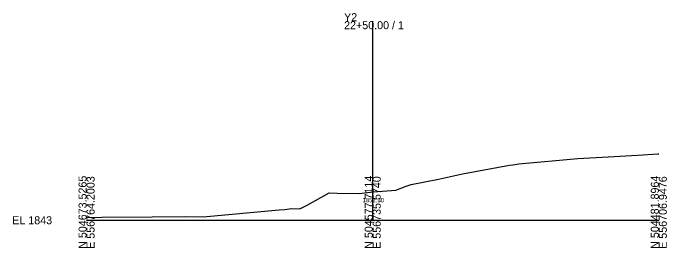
# Model space of a CAD drawing. Extents: x -26 to 1503, y -10 to 3574.
# Drawn here: x -25.7 to 202.8, y 2490.3 to 2572.5 of the extents above; entities that cross this region are included whole.
import ezdxf

# ---------------------------------------------------------------- set-up
doc = ezdxf.new("R2010")
doc.units = 0
for name, color, linetype in [('Default', 7, 'Continuous'), ('Exist Cross Section Cell', 7, 'Continuous'), ('Exist XS Center Line Elevation Label', 7, 'Continuous'), ('Exist XS Ground Line', 7, 'Continuous')]:
    doc.layers.add(name, color=color, linetype=linetype)

msp = doc.modelspace()

# ---------------------------------------------------------------- linework, layer by layer
at = {"layer": 'Exist Cross Section Cell'}
for p, q in [((100, 2500), (100, 2569.7)), ((0, 2500), (100, 2500)), ((100, 2500), (200, 2500))]:
    msp.add_line(p, q, dxfattribs=at)
at = {"layer": 'Exist XS Ground Line'}
for p, q in [((192.53, 2522.81), (199.62, 2523.21)), ((199.62, 2523.21), (200, 2523.23)), ((151.1, 2519.75), (171.67, 2521.65)), ((171.67, 2521.65), (182.26, 2522.17)), ((182.26, 2522.17), (192.53, 2522.81)), ((131.38, 2516.25), (147.87, 2519.26)), ((147.87, 2519.26), (148.96, 2519.45)), ((148.96, 2519.45), (151.1, 2519.75)), ((123.04, 2514.43), (131.38, 2516.25)), ((113.46, 2512.49), (123.04, 2514.43)), ((108.08, 2510.58), (111.73, 2511.9)), ((111.73, 2511.9), (113.46, 2512.49)), ((77.05, 2505.23), (84.73, 2509.64)), ((84.73, 2509.64), (87.63, 2509.51)), ((87.63, 2509.51), (95.33, 2509.41)), ((95.33, 2509.41), (100.23, 2509.93)), ((100.23, 2509.93), (108.08, 2510.58)), ((74.55, 2503.95), (77.05, 2505.23)), ((40.8, 2501.16), (67.27, 2503.69)), ((67.27, 2503.69), (69.32, 2503.73)), ((69.32, 2503.73), (71.67, 2504.13)), ((71.67, 2504.13), (74.55, 2503.95)), ((0, 2500.97), (5.28, 2501.11)), ((5.28, 2501.11), (22.87, 2501.16)), ((22.87, 2501.16), (34.65, 2501.28)), ((34.65, 2501.28), (40.8, 2501.16))]:
    msp.add_line(p, q, dxfattribs=at)

# ---------------------------------------------------------------- texts
at = {"layer": 'Default'}
msp.add_text('-', height=0.0001, dxfattribs=at).set_placement((0, 2500))
at = {"layer": 'Exist Cross Section Cell'}
for s, p in [('Y2', (90, 2569.7)), ('22+50.00 / 1', (90, 2566.9)), ('EL 1843', (-26, 2498.6))]:
    msp.add_text(s, height=2.8, dxfattribs=at).set_placement(p)
for s, p in [('N 504673.5265', (0, 2490)), ('E 556764.2003', (2.8, 2490)), ('N 504577.7114', (100, 2490)), ('E 556735.5740', (102.8, 2490)), ('N 504481.8964', (200, 2490)), ('E 556706.9476', (202.8, 2490))]:
    msp.add_text(s, height=2.8, rotation=90, dxfattribs=at).set_placement(p)
at = {"layer": 'Exist XS Center Line Elevation Label'}
msp.add_text('1852.90', height=1.5, dxfattribs=at).set_placement((96.47, 2506.31))

doc.saveas('drawing.dxf')
